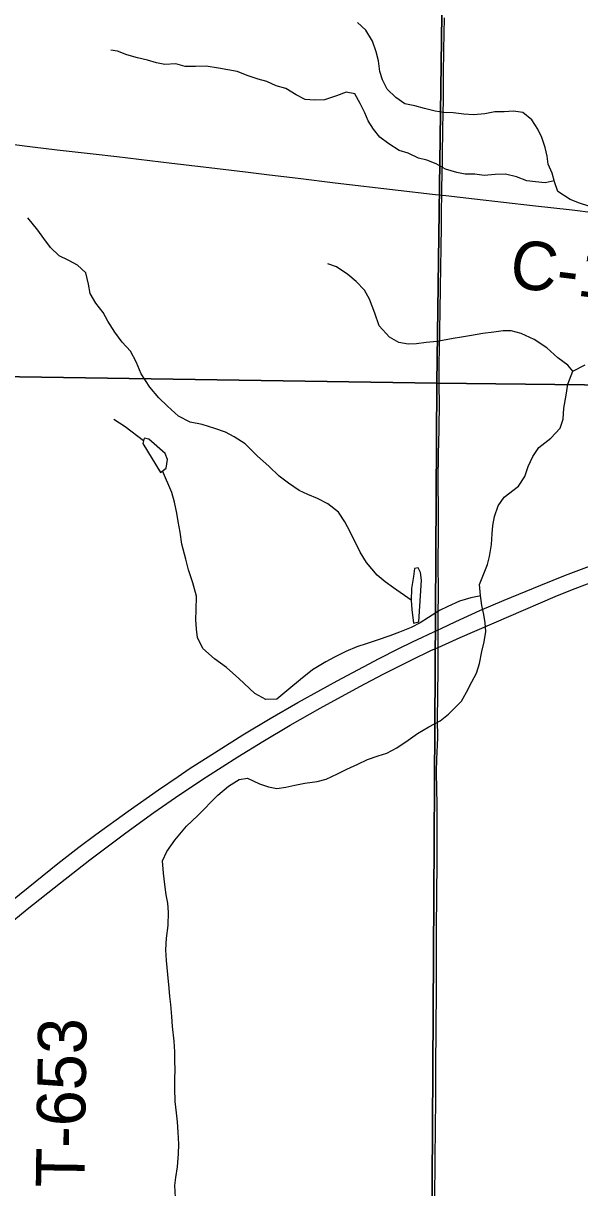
# Model space of a CAD drawing. Extents: x 0 to 34, y 0 to 22.
# Drawn here: x 10.139 to 10.791, y 10.337 to 11.702 of the extents above; entities that cross this region are included whole.
import ezdxf

# ---------------------------------------------------------------- set-up
doc = ezdxf.new("R2010")
doc.units = 0
for name, color, linetype in [('GM_X_County_Road', 7, 'Continuous'), ('GM_X_County_Road_Text', 7, 'Continuous'), ('GM_X_Interstate_Route', 7, 'Continuous'), ('GM_X_Minor_River', 7, 'Continuous'), ('GM_X_Section', 7, 'Continuous'), ('GM_X_Township_Road', 7, 'Continuous'), ('GM_X_Township_Road_Text', 7, 'Continuous')]:
    doc.layers.add(name, color=color, linetype=linetype)

msp = doc.modelspace()

# ---------------------------------------------------------------- linework, layer by layer
at = {"layer": 'GM_X_County_Road'}
for points in [[(10.1223, 11.5603), (10.1286, 11.5595), (10.1502, 11.5569), (10.1791, 11.5534), (10.2212, 11.5486), (10.2489, 11.5455), (10.3135, 11.5378), (10.3505, 11.5334), (10.3998, 11.5275), (10.4276, 11.5242), (10.4614, 11.52), (10.5045, 11.5148), (10.5785, 11.506), (10.6186, 11.5015), (10.6295, 11.5003)], [(10.6295, 11.5003), (10.634, 11.4999), (10.6679, 11.4958), (10.7358, 11.4882), (10.782, 11.4831), (10.8067, 11.4801), (10.8621, 11.4725), (10.9144, 11.4654), (10.9576, 11.4597), (11.0073, 11.453), (11.0357, 11.449), (11.0621, 11.4454), (11.0825, 11.4426), (11.1082, 11.4391), (11.133, 11.4354), (11.1854, 11.4283), (11.2285, 11.4229), (11.2563, 11.4194), (11.2655, 11.4179), (11.2747, 11.4158), (11.2837, 11.4133), (11.2925, 11.4102), (11.3012, 11.4065), (11.3083, 11.403)]]:
    msp.add_lwpolyline(points, dxfattribs=at)
at = {"layer": 'GM_X_Interstate_Route'}
for points in [[(10.1269, 10.6741), (10.18, 10.7171), (10.2045, 10.7362), (10.2244, 10.7511), (10.2621, 10.7784), (10.2978, 10.8032), (10.3208, 10.8191), (10.3336, 10.8278), (10.3677, 10.8494), (10.3965, 10.8677), (10.4285, 10.8869), (10.4607, 10.9056), (10.4878, 10.9207), (10.5069, 10.9311), (10.5563, 10.9573), (10.5784, 10.9686), (10.5951, 10.9767), (10.6252, 10.9907), (10.6289, 10.9924), (10.6458, 11.0004), (10.674, 11.0133), (10.7025, 11.0257), (10.7456, 11.0433), (10.7745, 11.0548), (10.8442, 11.0812)], [(10.1195, 10.6432), (10.144, 10.6634), (10.1828, 10.6944), (10.2172, 10.7211), (10.2595, 10.7529), (10.2922, 10.7767), (10.3229, 10.798), (10.354, 10.8185), (10.3907, 10.842), (10.4198, 10.86), (10.452, 10.879), (10.4871, 10.8989), (10.5334, 10.9245), (10.5609, 10.939), (10.5943, 10.9557), (10.6168, 10.9665), (10.6251, 10.9703), (10.6508, 10.9819), (10.7078, 11.0066), (10.7622, 11.0297), (10.7824, 11.038), (10.8144, 11.0501)]]:
    msp.add_lwpolyline(points, dxfattribs=at)
at = {"layer": 'GM_X_Minor_River'}
for points in [[(10.7652, 11.5046), (10.7615, 11.5157), (10.7586, 11.5259), (10.7541, 11.5366), (10.7527, 11.5461), (10.7505, 11.556), (10.7465, 11.5678), (10.742, 11.5777), (10.7349, 11.5884), (10.7244, 11.5972), (10.7134, 11.5985), (10.7024, 11.5978), (10.6914, 11.5979), (10.68, 11.5954), (10.6664, 11.5944), (10.6551, 11.5952), (10.6429, 11.5969), (10.632, 11.597), (10.6218, 11.5986), (10.6093, 11.6018), (10.598, 11.6049), (10.5862, 11.6073), (10.5757, 11.6146), (10.5656, 11.6246), (10.56, 11.6353), (10.557, 11.6451), (10.5552, 11.6577), (10.5527, 11.6683), (10.5482, 11.6809), (10.5404, 11.6935), (10.5306, 11.7027)], [(10.7611, 11.5171), (10.7505, 11.5146), (10.7392, 11.5159), (10.729, 11.5171), (10.7169, 11.5218), (10.7041, 11.525), (10.6919, 11.5243), (10.6791, 11.5233), (10.6681, 11.5249), (10.6567, 11.525), (10.6469, 11.527), (10.6337, 11.5309), (10.6228, 11.5371), (10.6118, 11.5414), (10.602, 11.5438), (10.5899, 11.5496), (10.5797, 11.5527), (10.5673, 11.5604), (10.5568, 11.5681), (10.5496, 11.5777), (10.5433, 11.5872), (10.5392, 11.5968), (10.534, 11.6078), (10.5276, 11.6189), (10.5174, 11.6209), (10.506, 11.6168), (10.492, 11.612), (10.4803, 11.6117), (10.4693, 11.6122), (10.4591, 11.618), (10.447, 11.6253), (10.4357, 11.6285), (10.4244, 11.6335), (10.4146, 11.6363), (10.4029, 11.6402), (10.3897, 11.6453), (10.3791, 11.6473), (10.3681, 11.6489), (10.3537, 11.6513), (10.3412, 11.651), (10.3291, 11.6512), (10.3182, 11.6543), (10.3053, 11.6533), (10.2955, 11.6553), (10.2849, 11.6584), (10.2732, 11.6612), (10.2607, 11.6647), (10.2498, 11.669), (10.2418, 11.6702)], [(10.9919, 11.4595), (10.9832, 11.4621), (10.9718, 11.4639), (10.9593, 11.4643), (10.9494, 11.4654), (10.938, 11.4669), (10.9244, 11.4687), (10.9126, 11.4691), (10.8997, 11.4694), (10.8849, 11.4709), (10.8743, 11.472), (10.864, 11.4735), (10.8504, 11.4765), (10.8394, 11.4787), (10.8291, 11.4802), (10.8173, 11.4832), (10.8018, 11.4873), (10.7908, 11.4907), (10.7797, 11.4952), (10.7652, 11.5046)], [(10.5934, 11.0256), (10.5728, 11.04), (10.5633, 11.0472), (10.5538, 11.0548), (10.5413, 11.0699), (10.534, 11.082), (10.5222, 11.1055), (10.5161, 11.1173), (10.5085, 11.1286), (10.4959, 11.1384), (10.4838, 11.1449), (10.4727, 11.1494), (10.4625, 11.1543), (10.45, 11.1626), (10.4389, 11.1709), (10.4271, 11.1826), (10.4138, 11.1943), (10.3994, 11.2087), (10.3864, 11.217), (10.3762, 11.2223), (10.3637, 11.2268), (10.3488, 11.2313), (10.3348, 11.2343), (10.3211, 11.2411), (10.3082, 11.2528), (10.2983, 11.2627), (10.2876, 11.2752), (10.2774, 11.2907), (10.2716, 11.3051), (10.2648, 11.3176), (10.2552, 11.3278), (10.2465, 11.3395), (10.2385, 11.3524), (10.2331, 11.3626), (10.2244, 11.3736), (10.2179, 11.385), (10.2156, 11.396), (10.2125, 11.4092), (10.203, 11.4183), (10.192, 11.424), (10.1814, 11.4293), (10.1711, 11.4391), (10.1635, 11.4493), (10.1566, 11.4592), (10.1448, 11.4735)], [(10.783, 11.2938), (10.7769, 11.3009), (10.7655, 11.3096), (10.7526, 11.3214), (10.7377, 11.3312), (10.7222, 11.338), (10.7108, 11.3413), (10.7013, 11.3413), (10.6903, 11.3398), (10.6774, 11.3382), (10.6641, 11.3359), (10.6524, 11.334), (10.6429, 11.3324), (10.624, 11.3289), (10.6111, 11.3274), (10.5997, 11.3262), (10.5902, 11.3258), (10.5792, 11.3277), (10.5682, 11.3337), (10.556, 11.3473), (10.551, 11.3621), (10.5449, 11.3784), (10.5388, 11.389), (10.5293, 11.3992), (10.5194, 11.4072), (10.5061, 11.4162), (10.4962, 11.4196)], [(10.6646, 10.9299), (10.6699, 10.9401), (10.6736, 10.9512), (10.6762, 10.9656), (10.6789, 10.9766), (10.6811, 10.9888), (10.6803, 10.999), (10.6788, 11.0089), (10.6765, 11.0195), (10.6749, 11.0312), (10.6737, 11.0441), (10.6782, 11.0555), (10.6831, 11.0673), (10.6854, 11.0768), (10.6876, 11.0908), (10.6883, 11.1034), (10.6891, 11.1132), (10.6913, 11.1235), (10.6955, 11.136), (10.7026, 11.1463), (10.7193, 11.1592), (10.7268, 11.1706), (10.7306, 11.1824), (10.7359, 11.1938), (10.7431, 11.2045), (10.7571, 11.2155), (10.768, 11.2273), (10.7714, 11.2379), (10.7725, 11.2508), (10.7751, 11.266), (10.777, 11.2786), (10.783, 11.2938), (10.7974, 11.3014)], [(10.2803, 11.2125), (10.2586, 11.2288), (10.2453, 11.2375)], [(10.3001, 11.1754), (10.3069, 11.1804), (10.3084, 11.1906), (10.3057, 11.1974), (10.2863, 11.2144), (10.281, 11.2156), (10.2795, 11.2091)], [(10.2795, 11.2091), (10.3001, 11.1754)], [(10.675, 11.0306), (10.6635, 11.0285), (10.6503, 11.0243), (10.6366, 11.0182), (10.6268, 11.0133), (10.6139, 11.0052), (10.6041, 10.9991), (10.5935, 10.9934), (10.5798, 10.9881), (10.5685, 10.9839), (10.5537, 10.9789), (10.5419, 10.975), (10.5298, 10.9708), (10.5169, 10.9655), (10.504, 10.9586), (10.4938, 10.9533), (10.4779, 10.9441), (10.4639, 10.9327), (10.4503, 10.9213), (10.4363, 10.9095), (10.4234, 10.909), (10.4105, 10.9162), (10.3918, 10.9336), (10.3774, 10.9468), (10.3633, 10.957), (10.3496, 10.9691), (10.3435, 10.982), (10.3423, 10.9915), (10.3416, 11.0029), (10.3419, 11.0139), (10.3422, 11.0302), (10.338, 11.0458), (10.3327, 11.0613), (10.3296, 11.0738), (10.325, 11.0912), (10.323, 11.1053), (10.3207, 11.1178), (10.3192, 11.1276), (10.3165, 11.1405), (10.3134, 11.1519), (10.3023, 11.177)], [(10.5965, 10.9987), (10.6025, 11.0003), (10.6058, 11.0489), (10.6046, 11.058), (10.6016, 11.0636), (10.5974, 11.0629), (10.5963, 11.0534), (10.5941, 11.0393), (10.5934, 11.0253), (10.5942, 11.0147)], [(10.5942, 11.0147), (10.5965, 10.9987)], [(10.3178, 10.3255), (10.317, 10.3396), (10.3181, 10.349), (10.3199, 10.3616), (10.321, 10.3768), (10.3214, 10.3881), (10.3206, 10.4022), (10.3198, 10.4143), (10.319, 10.4249), (10.3174, 10.4382), (10.317, 10.4534), (10.317, 10.4648), (10.3173, 10.475), (10.3169, 10.4856), (10.3169, 10.4963), (10.3161, 10.5088), (10.3141, 10.5258), (10.3133, 10.5376), (10.3122, 10.5516), (10.311, 10.5611), (10.3102, 10.571), (10.3086, 10.5869), (10.3071, 10.6032), (10.3063, 10.6157), (10.307, 10.6294), (10.3089, 10.6442), (10.3096, 10.6598), (10.3088, 10.6704), (10.3068, 10.6803), (10.3053, 10.6924), (10.3037, 10.7057), (10.3026, 10.7201), (10.3075, 10.7311), (10.3169, 10.7444), (10.3305, 10.7608), (10.3434, 10.773), (10.3672, 10.7969), (10.3797, 10.8076), (10.3922, 10.8156), (10.402, 10.8168), (10.4161, 10.8104), (10.4267, 10.807), (10.4362, 10.8047), (10.4468, 10.8063), (10.4574, 10.8086), (10.4692, 10.8113), (10.4836, 10.8132), (10.4942, 10.8159), (10.5075, 10.822), (10.5181, 10.8277), (10.5313, 10.8335), (10.5423, 10.8388), (10.5548, 10.843), (10.5651, 10.8461), (10.5768, 10.8526), (10.5901, 10.8614), (10.601, 10.8694), (10.6143, 10.877), (10.6275, 10.8842), (10.6374, 10.8919), (10.6525, 10.9071), (10.6585, 10.9177), (10.6646, 10.9299)]]:
    msp.add_lwpolyline(points, dxfattribs=at)
at = {"layer": 'GM_X_Section'}
for points in [[(9.6282, 12.3011), (10.6374, 12.2875), (10.6237, 11.2801), (9.6203, 11.2953)], [(11.5959, 12.2894), (11.5914, 11.2691), (10.6237, 11.2801), (10.6374, 12.2875)], [(9.6203, 11.2953), (10.6237, 11.2801), (10.6178, 10.275), (9.605, 10.2746)], [(10.6237, 11.2801), (11.5914, 11.2691), (11.591, 11.2544), (11.5843, 10.269), (10.6178, 10.275)]]:
    msp.add_lwpolyline(points, close=True, dxfattribs=at)
at = {"layer": 'GM_X_Township_Road'}
for points in [[(10.6295, 11.5003), (10.6295, 11.5049), (10.63, 11.528), (10.6301, 11.5373), (10.6304, 11.5467), (10.6308, 11.5777), (10.631, 11.5963), (10.6313, 11.6116), (10.6313, 11.6277), (10.6314, 11.6415), (10.6318, 11.6705), (10.6325, 11.708)], [(10.6254, 11.1567), (10.6254, 11.1657), (10.6255, 11.1967), (10.6263, 11.2251), (10.6266, 11.2583), (10.6264, 11.2743), (10.6265, 11.3054), (10.6266, 11.3177), (10.627, 11.3425), (10.6275, 11.3642), (10.6279, 11.3922), (10.6287, 11.4388), (10.6291, 11.4636), (10.6293, 11.4822), (10.6295, 11.5003)], [(10.6234, 10.8246), (10.6237, 10.8393), (10.6247, 10.8643), (10.6245, 10.8858), (10.625, 10.9144), (10.6252, 10.945), (10.6251, 10.9703), (10.6251, 10.9761), (10.6252, 10.9907), (10.6254, 11.0072), (10.6255, 11.0351), (10.6254, 11.0693), (10.6255, 11.1035), (10.6255, 11.1377), (10.6254, 11.1567)], [(10.6202, 10.2765), (10.621, 10.3016), (10.6212, 10.3108), (10.6218, 10.3818), (10.6221, 10.3958), (10.6222, 10.4141), (10.6223, 10.4328), (10.6223, 10.4483), (10.6223, 10.4701), (10.6225, 10.4918), (10.6227, 10.5104), (10.623, 10.5352), (10.6232, 10.5569), (10.6233, 10.5756), (10.6234, 10.588), (10.6234, 10.6097), (10.6233, 10.6408), (10.624, 10.7185), (10.6242, 10.7496), (10.6242, 10.7744), (10.6242, 10.7868), (10.6238, 10.8039), (10.6234, 10.8246)]]:
    msp.add_lwpolyline(points, dxfattribs=at)

# ---------------------------------------------------------------- texts
at = {"layer": 'GM_X_County_Road_Text'}
msp.add_text('C-1302', height=0.05682, rotation=352.7357, dxfattribs=at).set_placement((10.7071, 11.3928))
at = {"layer": 'GM_X_Township_Road_Text'}
msp.add_text('T-653', height=0.05682, rotation=89.1691, dxfattribs=at).set_placement((10.2108, 10.337))

doc.saveas('drawing.dxf')
